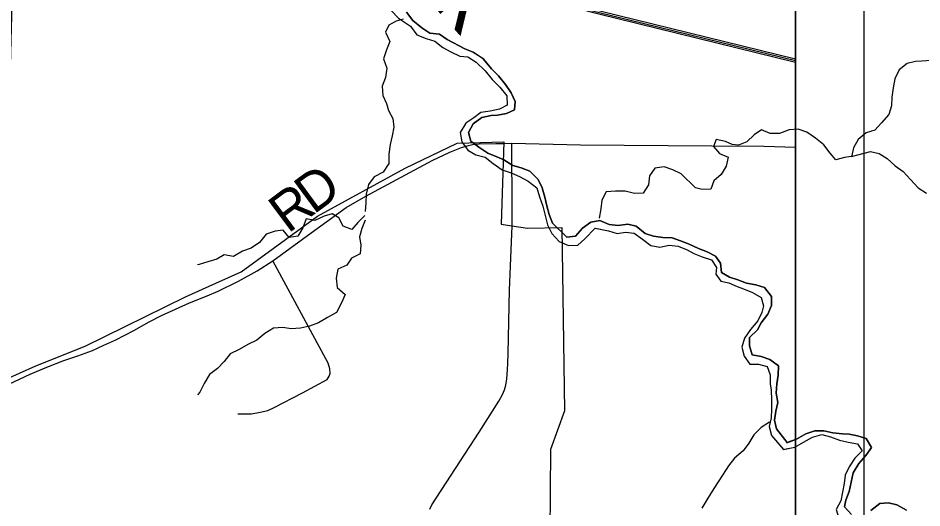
# Model space of a CAD drawing. Extents: x 0 to 34, y 0 to 22.
# Drawn here: x 12.978 to 14.298, y 8.496 to 9.211 of the extents above; entities that cross this region are included whole.
import ezdxf

# ---------------------------------------------------------------- set-up
doc = ezdxf.new("R2010")
doc.units = 0
for name, color, linetype in [('GM_X_Corporation', 7, 'Continuous'), ('GM_X_County_Road', 7, 'Continuous'), ('GM_X_County_Road_Text', 7, 'Continuous'), ('GM_X_Major_River', 7, 'Continuous'), ('GM_X_Major_River_Text', 7, 'Continuous'), ('GM_X_Minor_River', 7, 'Continuous'), ('GM_X_Rail_Line', 7, 'Continuous'), ('GM_X_Township_Road', 7, 'Continuous'), ('SH_Cut_Line', 7, 'Continuous'), ('SH_Data', 7, 'Continuous')]:
    doc.layers.add(name, color=color, linetype=linetype)

msp = doc.modelspace()

# ---------------------------------------------------------------- linework, layer by layer
at = {"layer": 'GM_X_Corporation'}
for points in [[(14.1135, 7.5799), (14.1135, 10.1047), (13.8002, 10.1009), (13.7966, 9.9333), (13.7275, 9.9315), (13.6987, 9.9173), (13.6816, 9.9572), (13.6438, 10.0496), (13.6177, 10.1659), (13.6021, 10.2777), (13.606, 10.4076), (12.9927, 10.4066), (12.9728, 9.4593)], [(12.9564, 8.6818), (13.0041, 8.7033), (13.0761, 8.7321), (13.2229, 8.8042), (13.267, 8.824), (13.304, 8.8406), (13.4155, 8.9216), (13.5436, 8.9919), (13.6194, 9.0287), (13.6875, 9.0304), (13.6837, 8.9101), (13.6996, 8.9077), (13.7222, 8.9044), (13.7725, 8.9055), (13.7761, 8.6374), (13.756, 8.5811), (13.7547, 8.4582)]]:
    msp.add_lwpolyline(points, dxfattribs=at)
at = {"layer": 'GM_X_County_Road'}
msp.add_line((13.6997, 8.9298), (13.6992, 9.0283), dxfattribs=at)
for points in [[(12.9572, 8.6731), (12.9961, 8.6909), (13.0202, 8.7012), (13.0448, 8.7108), (13.0653, 8.7177), (13.0871, 8.7258), (13.1033, 8.7332), (13.121, 8.7411), (13.1475, 8.7547), (13.1699, 8.7673), (13.1878, 8.7769), (13.2083, 8.7862), (13.2288, 8.795), (13.2546, 8.8053), (13.2703, 8.8122), (13.3, 8.827), (13.3273, 8.842), (13.3504, 8.8565), (13.4062, 8.8975), (13.4573, 8.9344), (13.4861, 8.9509), (13.5832, 9.0032), (13.609, 9.0153), (13.6257, 9.0221), (13.6343, 9.0248), (13.6421, 9.0263), (13.6515, 9.0273), (13.6761, 9.028), (13.6876, 9.0282)], [(13.6876, 9.0282), (13.6992, 9.0283), (13.7997, 9.0261), (13.9914, 9.0248)], [(13.9914, 9.0248), (14.0674, 9.0239), (14.1135, 9.0227)], [(13.5795, 8.4937), (13.5827, 8.5003), (13.6517, 8.6065), (13.6805, 8.6517), (13.6857, 8.6611), (13.6886, 8.6682), (13.6906, 8.6751), (13.692, 8.6844), (13.693, 8.6974), (13.6933, 8.707), (13.6938, 8.721), (13.6962, 8.8142), (13.6998, 8.9072), (13.6997, 8.9298)]]:
    msp.add_lwpolyline(points, dxfattribs=at)
at = {"layer": 'GM_X_Major_River'}
for points in [[(13.5127, 9.2329), (13.534, 9.2109)], [(13.6582, 9.1513), (13.6427, 9.1615), (13.6309, 9.1664), (13.605, 9.1799), (13.5935, 9.1878), (13.5798, 9.1892), (13.568, 9.1972), (13.555, 9.2077), (13.5454, 9.2198)], [(13.5454, 9.2198), (13.555, 9.2077), (13.568, 9.1972), (13.5798, 9.1892), (13.5935, 9.1878), (13.605, 9.1799), (13.6309, 9.1664), (13.6427, 9.1615), (13.6583, 9.1515)], [(13.5336, 9.2112), (13.5513, 9.1993), (13.5608, 9.1869), (13.5742, 9.1812), (13.5871, 9.1775), (13.5986, 9.1681), (13.6104, 9.1621), (13.6234, 9.1557), (13.6352, 9.1546), (13.6474, 9.1467), (13.6604, 9.1343), (13.6707, 9.1214), (13.6818, 9.1101), (13.6921, 9.0976), (13.6926, 9.0839), (13.6813, 9.0782), (13.6676, 9.0754), (13.6539, 9.0734), (13.6441, 9.0654), (13.632, 9.0577), (13.6241, 9.044), (13.6261, 9.0304), (13.6349, 9.0183), (13.6467, 9.0115), (13.6604, 9.0078), (13.6723, 8.9987), (13.6852, 8.9897), (13.6982, 8.9852), (13.7108, 8.9796), (13.7234, 8.9728), (13.736, 8.963), (13.7398, 8.9501), (13.7445, 8.9365), (13.7515, 8.9092), (13.7577, 8.8963), (13.7684, 8.885), (13.7821, 8.879), (13.7958, 8.8794), (13.806, 8.8886), (13.821, 8.9041)], [(13.534, 9.2109), (13.5513, 9.1993), (13.5608, 9.1869), (13.5742, 9.1812), (13.5871, 9.1775), (13.5986, 9.1681), (13.6104, 9.1621), (13.6234, 9.1557), (13.6352, 9.1546), (13.6474, 9.1467), (13.6604, 9.1343), (13.6707, 9.1214), (13.6818, 9.1101), (13.6921, 9.0976), (13.6926, 9.0839), (13.6813, 9.0782), (13.6676, 9.0754), (13.6539, 9.0734), (13.6441, 9.0654), (13.632, 9.0577), (13.6241, 9.044), (13.6261, 9.0304), (13.6349, 9.0183), (13.6467, 9.0115), (13.6604, 9.0078), (13.6723, 8.9987), (13.6852, 8.9897), (13.6982, 8.9852), (13.7108, 8.9796), (13.7234, 8.9728), (13.736, 8.963), (13.7398, 8.9501), (13.7445, 8.9365), (13.7515, 8.9092), (13.7577, 8.8963), (13.7684, 8.885), (13.7821, 8.879), (13.7958, 8.8794), (13.806, 8.8886), (13.821, 8.9042)], [(13.7799, 8.8911), (13.7587, 8.9115), (13.7541, 8.9244), (13.7506, 8.9369), (13.7474, 8.9494), (13.7436, 8.9631), (13.7378, 8.9756), (13.7259, 8.9876), (13.713, 8.9925), (13.7008, 8.9959), (13.6878, 9.0041), (13.6775, 9.0083), (13.6642, 9.0139), (13.6512, 9.0225), (13.6397, 9.0312), (13.6362, 9.0441), (13.643, 9.0567), (13.6555, 9.0659), (13.6691, 9.069), (13.6786, 9.0694), (13.6916, 9.0718), (13.7033, 9.0772), (13.704, 9.0893), (13.6986, 9.1018), (13.6901, 9.1143), (13.6798, 9.1268), (13.6699, 9.137), (13.6582, 9.1513)], [(13.6582, 9.1513), (13.6699, 9.137), (13.6798, 9.1268), (13.6901, 9.1143), (13.6986, 9.1018), (13.704, 9.0893), (13.7033, 9.0772), (13.6916, 9.0718), (13.6786, 9.0694), (13.6691, 9.069), (13.6555, 9.0659), (13.643, 9.0567), (13.6362, 9.0441), (13.6397, 9.0312), (13.6512, 9.0225), (13.6642, 9.0139), (13.6775, 9.0083), (13.6878, 9.0041), (13.7008, 8.9959), (13.713, 8.9925), (13.7259, 8.9876), (13.7378, 8.9756), (13.7436, 8.9631), (13.7474, 8.9494), (13.7506, 8.9369), (13.7541, 8.9244), (13.7587, 8.9115), (13.7802, 8.8909)], [(13.7797, 8.8911), (13.7923, 8.8927), (13.8025, 8.9042), (13.8146, 8.913), (13.8279, 8.9157), (13.8416, 8.9097), (13.8549, 8.9083), (13.8686, 8.9102), (13.8811, 8.9073), (13.8941, 8.8963), (13.9063, 8.8926), (13.92, 8.8908), (13.9337, 8.8901), (13.9459, 8.886), (13.9584, 8.8811), (13.9722, 8.8748), (13.9847, 8.8695), (13.9969, 8.8635), (14.0042, 8.8533), (14.0055, 8.8396), (14.0173, 8.8329), (14.0295, 8.8288), (14.042, 8.8239), (14.0557, 8.8213), (14.0683, 8.8176), (14.0787, 8.8047), (14.0787, 8.7911), (14.0731, 8.7785), (14.0637, 8.7659), (14.0584, 8.756), (14.0464, 8.7445), (14.0464, 8.7324), (14.0503, 8.7191), (14.0633, 8.7169), (14.0762, 8.7124), (14.0888, 8.7034), (14.0885, 8.6897), (14.0863, 8.6768), (14.0856, 8.6631), (14.088, 8.6498), (14.0851, 8.6369), (14.0832, 8.624), (14.086, 8.6111), (14.101, 8.5917)], [(14.1014, 8.5911), (14.086, 8.6111), (14.0832, 8.624), (14.0851, 8.6369), (14.088, 8.6498), (14.0856, 8.6631), (14.0863, 8.6768), (14.0885, 8.6897), (14.0888, 8.7034), (14.0762, 8.7124), (14.0633, 8.7169), (14.0503, 8.7191), (14.0464, 8.7324), (14.0464, 8.7445), (14.0584, 8.756), (14.0637, 8.7659), (14.0731, 8.7785), (14.0787, 8.7911), (14.0787, 8.8047), (14.0683, 8.8176), (14.0557, 8.8213), (14.042, 8.8239), (14.0295, 8.8288), (14.0173, 8.8329), (14.0055, 8.8396), (14.0042, 8.8533), (13.9969, 8.8635), (13.9847, 8.8695), (13.9722, 8.8748), (13.9584, 8.8811), (13.9459, 8.886), (13.9337, 8.8901), (13.92, 8.8908), (13.9063, 8.8926), (13.8941, 8.8963), (13.8811, 8.9073), (13.8686, 8.9102), (13.8549, 8.9083), (13.8416, 8.9097), (13.8279, 8.9157), (13.8146, 8.913), (13.8025, 8.9042), (13.7923, 8.8927), (13.7799, 8.8911)], [(13.821, 8.9042), (13.8405, 8.9006), (13.8534, 8.8965), (13.8652, 8.8984), (13.8781, 8.897), (13.89, 8.8883), (13.9026, 8.8789), (13.9155, 8.8767), (13.9292, 8.8794), (13.9425, 8.878), (13.9555, 8.8728), (13.965, 8.8675), (13.9772, 8.8626), (13.9909, 8.8582), (13.9982, 8.8468), (13.9971, 8.8373), (14.0044, 8.8267), (14.0162, 8.8245), (14.0284, 8.8189), (14.0379, 8.8155), (14.0509, 8.8103), (14.0635, 8.8031), (14.067, 8.791), (14.0644, 8.7811), (14.0587, 8.7689), (14.0478, 8.7563), (14.0391, 8.7434), (14.0354, 8.7304), (14.0389, 8.7175), (14.047, 8.7058), (14.0595, 8.7055), (14.0721, 8.7021), (14.0767, 8.69), (14.0768, 8.6771), (14.078, 8.6676), (14.0785, 8.6536), (14.0786, 8.6399), (14.0779, 8.627), (14.0753, 8.6144), (14.0784, 8.6015), (14.0961, 8.5812)], [(13.8215, 8.9041), (13.8405, 8.9006), (13.8534, 8.8965), (13.8652, 8.8984), (13.8781, 8.897), (13.89, 8.8883), (13.9026, 8.8789), (13.9155, 8.8767), (13.9292, 8.8794), (13.9425, 8.878), (13.9555, 8.8728), (13.965, 8.8675), (13.9772, 8.8626), (13.9909, 8.8582), (13.9982, 8.8468), (13.9971, 8.8373), (14.0044, 8.8267), (14.0162, 8.8245), (14.0284, 8.8189), (14.0379, 8.8155), (14.0509, 8.8103), (14.0635, 8.8031), (14.067, 8.791), (14.0644, 8.7811), (14.0587, 8.7689), (14.0478, 8.7563), (14.0391, 8.7434), (14.0354, 8.7304), (14.0389, 8.7175), (14.047, 8.7058), (14.0595, 8.7055), (14.0721, 8.7021), (14.0767, 8.69), (14.0768, 8.6771), (14.078, 8.6676), (14.0785, 8.6536), (14.0786, 8.6399), (14.0779, 8.627), (14.0753, 8.6144), (14.0784, 8.6015), (14.0958, 8.5815)], [(14.1008, 8.5909), (14.1153, 8.596), (14.129, 8.6041), (14.1419, 8.6084), (14.1552, 8.6084), (14.1681, 8.6055), (14.1822, 8.604), (14.1921, 8.6033), (14.2042, 8.6011), (14.2168, 8.597), (14.2245, 8.5841), (14.2166, 8.5723), (14.206, 8.5605), (14.1978, 8.5468), (14.1948, 8.5331), (14.1922, 8.5194), (14.1874, 8.5068), (14.1851, 8.4973), (14.1955, 8.486)], [(14.1955, 8.486), (14.1851, 8.4973), (14.1874, 8.5068), (14.1922, 8.5194), (14.1948, 8.5331), (14.1978, 8.5468), (14.206, 8.5605), (14.2166, 8.5723), (14.2245, 8.5841), (14.2168, 8.597), (14.2042, 8.6011), (14.1921, 8.6033), (14.1822, 8.604), (14.1681, 8.6055), (14.1552, 8.6084), (14.1419, 8.6084), (14.129, 8.6041), (14.1153, 8.596), (14.1014, 8.5911)], [(14.0953, 8.581), (14.1128, 8.5842), (14.1252, 8.5919), (14.1385, 8.5992), (14.1522, 8.6031), (14.1647, 8.5997), (14.1777, 8.5945), (14.1906, 8.5915), (14.2043, 8.5893), (14.2112, 8.5791), (14.2003, 8.5684), (14.192, 8.5558), (14.1864, 8.5433), (14.1849, 8.5311), (14.1823, 8.5186), (14.1798, 8.506), (14.173, 8.4934), (14.1769, 8.4805), (14.1981, 8.4737)], [(14.0961, 8.5812), (14.1128, 8.5842), (14.1252, 8.5919), (14.1385, 8.5992), (14.1522, 8.6031), (14.1647, 8.5997), (14.1777, 8.5945), (14.1906, 8.5915), (14.2043, 8.5893), (14.2112, 8.5791), (14.2003, 8.5684), (14.192, 8.5558), (14.1864, 8.5433), (14.1849, 8.5311), (14.1823, 8.5186), (14.1798, 8.506), (14.173, 8.4934), (14.1769, 8.4805), (14.1982, 8.4736)], [(14.2756, 8.4925), (14.2619, 8.5), (14.2493, 8.503), (14.2368, 8.5022), (14.2239, 8.4918)], [(14.2239, 8.4918), (14.2368, 8.5022), (14.2493, 8.503), (14.2619, 8.5), (14.2756, 8.4925)]]:
    msp.add_lwpolyline(points, dxfattribs=at)
at = {"layer": 'GM_X_Minor_River'}
for points in [[(13.5405, 9.2096), (13.5302, 9.2069), (13.5196, 9.2007), (13.5148, 9.1904), (13.521, 9.1771), (13.5165, 9.1646), (13.5121, 9.1516), (13.5168, 9.138), (13.515, 9.1246), (13.5102, 9.1117), (13.511, 9.098), (13.5161, 9.0863), (13.5192, 9.0764), (13.5254, 9.0643), (13.527, 9.0518), (13.5245, 9.0392), (13.5216, 9.0263), (13.5198, 9.0126), (13.5199, 8.9989), (13.5113, 8.9863), (13.4984, 8.9793), (13.4901, 8.9679), (13.4868, 8.9542), (13.4862, 8.9412), (13.4852, 8.9287)], [(14.3116, 9.1494), (14.2983, 9.1485), (14.2888, 9.1477), (14.2766, 9.145), (14.2653, 9.1354), (14.2586, 9.1224), (14.2561, 9.1095), (14.2546, 9.0958), (14.254, 9.0832), (14.2499, 9.0706), (14.2394, 9.058), (14.2296, 9.0477), (14.2167, 9.0438), (14.205, 9.0338), (14.1983, 9.0216), (14.1953, 9.0086)], [(14.1952, 9.009), (14.1851, 9.0074), (14.1726, 9.0039), (14.1641, 9.0141), (14.1553, 9.0262), (14.143, 9.036), (14.1304, 9.0446), (14.1178, 9.0491), (14.1045, 9.0479), (14.0905, 9.0428), (14.0768, 9.0427), (14.0642, 9.0479), (14.0533, 9.0406), (14.0427, 9.0303), (14.0306, 9.0256), (14.0211, 9.0263), (14.0115, 9.0308), (13.9978, 9.0337), (13.9937, 9.0238), (14.0029, 9.0132), (14.0152, 9.008), (14.0122, 8.9951), (14.0051, 8.9825), (13.9946, 8.9737), (13.9901, 8.9615), (13.9772, 8.9606), (13.9677, 8.9632), (13.9469, 8.9836), (13.9344, 8.9895), (13.9218, 8.994), (13.9081, 8.992), (13.9006, 8.9809), (13.8992, 8.9676), (13.8913, 8.9554), (13.8784, 8.9549), (13.8647, 8.9582), (13.851, 8.9585), (13.8373, 8.9572), (13.8306, 8.9454), (13.8292, 8.9325), (13.827, 8.9188)], [(14.1954, 9.0088), (14.2233, 9.0165), (14.2359, 9.0135), (14.2477, 9.006), (14.2592, 8.9954), (14.2707, 8.9872), (14.2815, 8.9754), (14.293, 8.9634), (14.3048, 8.9555)], [(13.4848, 8.9226), (13.4743, 8.9126), (13.4656, 8.9023), (13.453, 8.9072), (13.4468, 8.9193), (13.4369, 8.9253), (13.4252, 8.9218), (13.4115, 8.9156), (13.399, 8.9178), (13.3941, 8.9048), (13.387, 8.8926), (13.3741, 8.8906), (13.3656, 8.9015), (13.3535, 8.8999), (13.3406, 8.8956), (13.3308, 8.8834), (13.3187, 8.875), (13.3059, 8.8707), (13.293, 8.863), (13.2793, 8.8655), (13.2683, 8.859), (13.2554, 8.8551), (13.2429, 8.8512), (13.2404, 8.8509)], [(13.4853, 8.9158), (13.4801, 8.9036), (13.4771, 8.8918), (13.4787, 8.8796), (13.4777, 8.8667), (13.4652, 8.8605), (13.4585, 8.8502), (13.4452, 8.8444), (13.4427, 8.8314), (13.4443, 8.8178), (13.4558, 8.8076), (13.4506, 8.795), (13.4431, 8.7813), (13.4303, 8.7736), (13.417, 8.7659), (13.4038, 8.7612), (13.3909, 8.7581), (13.3772, 8.7572), (13.365, 8.759), (13.3513, 8.7581), (13.3385, 8.7504), (13.3268, 8.7409), (13.3139, 8.7343), (13.301, 8.727), (13.2882, 8.7208), (13.2791, 8.7093), (13.2697, 8.6994), (13.258, 8.6905), (13.2502, 8.6772), (13.2438, 8.6646), (13.2404, 8.6609)], [(14.0756, 8.6208), (14.0635, 8.6131), (14.0529, 8.6024), (14.0454, 8.5902), (14.0372, 8.5791), (14.0247, 8.5684), (14.0157, 8.5569), (14.0078, 8.545), (13.9996, 8.5321), (13.9921, 8.5202), (13.9842, 8.5076), (13.9767, 8.4954)]]:
    msp.add_lwpolyline(points, dxfattribs=at)
at = {"layer": 'GM_X_Rail_Line'}
for points in [[(8.873, 10.4647), (9.6892, 10.2593), (10.5917, 10.0331), (11.1811, 9.8802), (12.0186, 9.6724), (12.8863, 9.4545), (13.1526, 9.3886), (13.8266, 9.2172), (14.1135, 9.147)], [(8.8821, 10.4647), (9.6898, 10.2615), (10.5923, 10.0354), (11.1817, 9.8825), (12.0192, 9.6747), (12.8869, 9.4568), (13.1532, 9.3908), (13.8271, 9.2194), (14.1135, 9.1494)], [(9.1167, 10.404), (9.1537, 10.3972), (9.6904, 10.2638), (10.5928, 10.0376), (11.1823, 9.8847), (12.0197, 9.6769), (12.8874, 9.459), (13.1538, 9.3931), (13.8277, 9.2217), (14.1135, 9.1518)]]:
    msp.add_lwpolyline(points, dxfattribs=at)
msp.add_lwpolyline([(14.1135, 5.8645), (14.1135, 10.4074), (12.9952, 10.4123), (12.9843, 9.8218), (12.975, 9.4666), (12.9697, 9.2637), (12.9695, 9.2552), (12.9694, 9.2509), (12.9542, 8.6724), (12.9304, 7.7644), (12.9222, 7.4711), (12.9186, 7.3231), (12.9183, 7.3117), (12.9181, 7.3048), (12.8807, 5.8723), (13.2678, 5.8695), (13.384, 5.8688), (13.5036, 5.8681)], close=True, dxfattribs=at)
at = {"layer": 'GM_X_Township_Road'}
msp.add_lwpolyline([(13.2991, 8.6331), (13.3089, 8.633), (13.3189, 8.6333), (13.332, 8.6355), (13.343, 8.638), (13.3524, 8.6424), (13.3936, 8.6638), (13.4295, 8.6832), (13.4327, 8.6879), (13.4342, 8.6918), (13.4335, 8.6987), (13.431, 8.7069), (13.3504, 8.8565)], dxfattribs=at)
at = {"layer": 'SH_Cut_Line'}
msp.add_lwpolyline([(8.8581, 3.6647), (14.1135, 3.6647), (14.1135, 10.4647), (8.6408, 10.4647)], dxfattribs=at)
at = {"layer": 'SH_Data'}
for p, q in [((14.2135, 10.5647), (14.2135, 3.5647)), ((14.1135, 10.4647), (14.1135, 3.6647))]:
    msp.add_line(p, q, dxfattribs=at)

# ---------------------------------------------------------------- texts
at = {"layer": 'GM_X_County_Road_Text'}
for s, rotation, p in [('D', 36.3664, (13.4096, 8.9234)), ('R', 36.7637, (13.3723, 8.8956))]:
    msp.add_text(s, height=0.0568, rotation=rotation, dxfattribs=at).set_placement(p)
at = {"layer": 'GM_X_Major_River_Text'}
msp.add_text('Black', height=0.09473, rotation=312.0416, dxfattribs=at).set_placement((13.4169, 9.4149))

doc.saveas('drawing.dxf')
